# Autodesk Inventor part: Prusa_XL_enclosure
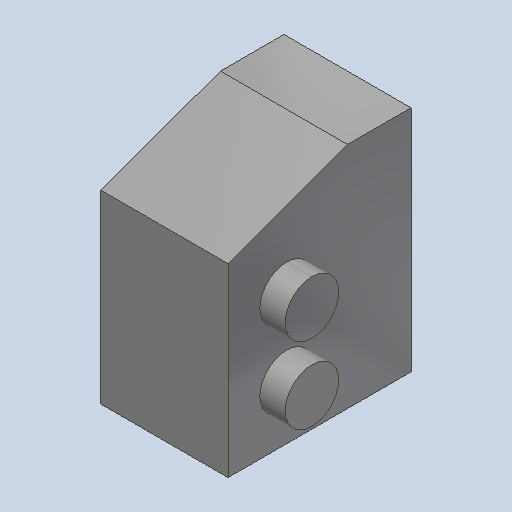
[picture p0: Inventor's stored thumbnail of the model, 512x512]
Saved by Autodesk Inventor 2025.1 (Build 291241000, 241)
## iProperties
Created: 2024-11
Part Number: Prusa_XL_enclosure
Material: 1.0037 S235JR
Document SubType Name: Modeling
Designer: BennF
Density: 7.85 g/cm^3
Appearance: Stahl
Author: BennF
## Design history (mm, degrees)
sketch "Sketch2"
  geometry: L1 (0, 0)-(0, 900); L2 (0, 900)-(-250, 900); L3 (-250, 900)-(-720, 728.934); L4 (-720, 728.934)-(-720, 0); L5 (-720, 0)-(0, 0)
  constraints: 10 end point, 2 perpendicular, 1 parallel, 1 vertical
  dimensions: "d0" = 900 distance of L1.start L1.end; "d1" = 720 distance of L4.end L1.start; "d2" = 250 distance of L1.end L2.end; "d3" = 160 deg angle of L3 L2
extrude "Extrusion1" new body sketch "Sketch2" stored distance "d4" = 500; taper "d5" = 0 deg
sketch "Sketch3"
  geometry: L1 (514.467, -489.904)-(364.467, -230.096); L2 (364.467, -230.096)-(214.467, -489.904); L3 (214.467, -489.904)-(514.467, -489.904); L4 (0, 0)-(0, -720) reference; L5 (0, -720)-(728.934, -720) reference; C1 r 105 at (514.467, -489.904); C2 r 105 at (214.467, -489.904); C3 r 105 at (364.467, -230.096); 4 further points
  constraints: 6 end point, 4 midpoint, 3 centre point, 3 coincident, 3 horizontal alignment, 2 equal radius, 2 vertical alignment, 1 equal length, 1 horizontal
  dimensions: "d6" = 210 diameter of C1; "d7" = 300 distance of L2.end L1.start
extrude "Extrusion2" join sketch "Sketch3" distance "d8" = 100; taper "d9" = 0 deg
sketch "Sketch4"
  geometry: C1 r 105 at (-514.467, -489.904) reference; C2 r 105 at (-214.467, -489.904) reference; 1 further point
extrude "Extrusion3" join sketch "Sketch4" distance "d10" = 100; taper "d11" = 0 deg
body "Solid1"
